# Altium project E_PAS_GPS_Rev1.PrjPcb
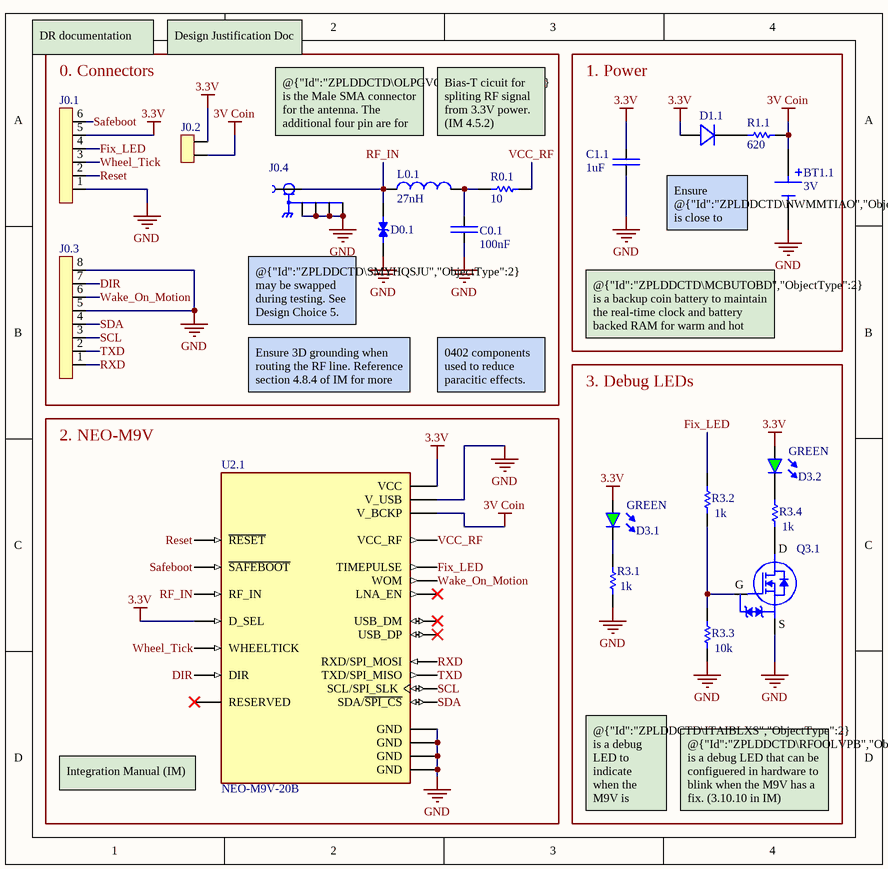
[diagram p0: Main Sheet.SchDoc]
1 sheet, 20 parts. Net scope: global (net labels, ports and power ports of the same name join across sheets).
Board file: Main Sheet.PcbDoc

## Sheet Main Sheet.SchDoc
size 165 x 160 mm; SheetNumber: 1; SheetTotal: 1

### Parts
BT1.1  3V  [BAT_MS621FE-FL11E]
C0.1  value 100nF  [CAPC1005X55N]  (hidden comment: 0402B104K160CT)
C1.1  1uF  [C0805]
D0.1  PESD0402-140  [DIO_PESD0402-140]  (value not drawn)
D1.1  VSKY20301608-G4-08  [VSKY20301608-G4-08-Footprint-1]  (value not drawn)
D3.1  GREEN  [WL-SMCW_0805_150080xx75000]
D3.2  GREEN  [WL-SMCW_0805_150080xx75000]
J0.1  0.1" Header 6pos Male  [0.1" Header 6pos Male-Footprint-1]  (value not drawn)
J0.2  0.1" Header 2pos  [0.1%22 Header 2pos]  (value not drawn)
J0.3  0.1" Header 8pos Male  [0.1" Header 8pos Male-Footprint-1]  (value not drawn)
J0.4  RF2-03E-T-00-50-G  [HUBER+SUHNER_85201239]  (value not drawn)
L0.1  value 27nH  [INDC1005X55N]  (hidden comment: LQG15HS27NJ02D)
Q3.1  DMN3023L-7  [SOT-23-3]  (value not drawn)
R0.1  value 10  [RESC1005X40N]  (hidden comment: RCS040210R0FKED)
R1.1  620  [0805 General Resistor Footprint-Footprint-1]
R3.1  1k  [0805 General Resistor Footprint-Footprint-1]
R3.2  1k  [0805 General Resistor Footprint-Footprint-1]
R3.3  10k  [0805 General Resistor Footprint-Footprint-1]
R3.4  1k  [0805 General Resistor Footprint-Footprint-1]
U2.1  NEO-M9V-20B  [XCVR_NEO-M9V-20B]

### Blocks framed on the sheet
0. Connectors: C0.1 D0.1 J0.1-J0.4 L0.1 R0.1
1. Power: BT1.1 C1.1 D1.1 R1.1
3. Debug LEDs: D3.1 D3.2 Q3.1 R3.1-R3.4
2. NEO-M9V: U2.1

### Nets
3.3V: C1.1.2 D1.1.2 D3.1.2(A) D3.2.2(A) J0.1.5 J0.2.2 U2.1.2(D_SEL) U2.1.23(VCC)
3V Coin: BT1.1.POS J0.2.1 R1.1.1 U2.1.22(V_BCKP)
GND: BT1.1.NEG C0.1.1 C1.1.1 D0.1.1 J0.1.1 J0.3.5 J0.3.8 J0.4.G1 J0.4.G2 J0.4.G3 J0.4.G4 Q3.1.2(S) R3.1.1 R3.3.1 U2.1.7(V_USB) U2.1.10(GND) U2.1.12(GND) U2.1.13(GND) U2.1.24(GND)
DIR: J0.3.7 U2.1.15(DIR)
Fix_LED: J0.1.4 R3.2.2 U2.1.3(TIMEPULSE)
Reset: J0.1.2 U2.1.8(~{RESET})
RF_IN: D0.1.2 J0.4.1 L0.1.1 U2.1.11(RF_IN)
RXD: J0.3.1 U2.1.21(RXD/SPI_MOSI)
Safeboot: J0.1.6 U2.1.1(~{SAFEBOOT})
SCL: J0.3.3 U2.1.19(SCL/SPI_SLK)
SDA: J0.3.4 U2.1.18(SDA/~{SPI_CS})
TXD: J0.3.2 U2.1.20(TXD/SPI_MISO)
VCC_RF: R0.1.2 U2.1.9(VCC_RF)
Wake_On_Motion: J0.3.6 U2.1.17(WOM)
Wheel_Tick: J0.1.3 U2.1.4(WHEELTICK)
NetC0.1_2: C0.1.2 L0.1.2 R0.1.1
NetD1.1_1: D1.1.1 R1.1.2
NetD3.1_1: D3.1.1(K) R3.1.2
NetD3.2_1: D3.2.1(K) R3.4.2
NetQ3.1_1: Q3.1.1(G) R3.2.1 R3.3.2
NetQ3.1_3: Q3.1.3(D) R3.4.1

Not connected (* = marked no-connect by the designer): U2.1 5(USB_DM)* 6(USB_DP)* 14(LNA_EN)* 16(RESERVED)*

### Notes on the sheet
- DR documentation
- DR documentation <https://docs.google.com/document/d/1GB34gBHzcDJZjTo_4NjgQijoAi6lwd67PKlUektAjk4/edit?tab=t.6ztd4vjw2t1h>
- Design Justification Doc
- Design Justification Doc <https://docs.google.com/document/d/1GB34gBHzcDJZjTo_4NjgQijoAi6lwd67PKlUektAjk4/edit?tab=t.6i3rtu1oc2nn>
- @{"Id":"ZPLDDCTD\OLPGVQHD","ObjectType":2} is the Male SMA connector for the antenna. The additional four pin are for shielding.
- Bias-T cicuit for spliting RF signal from 3.3V power. (IM 4.5.2)
- Ensure @{"Id":"ZPLDDCTD\NWMMTIAO","ObjectType":2} is close to VCC.
- (near D0.1) @{"Id":"ZPLDDCTD\SMYHQSJU","ObjectType":2} may be swapped during testing. See Design Choice 5.
- @{"Id":"ZPLDDCTD\MCBUTOBD","ObjectType":2} is a backup coin battery to maintain the real-time clock and battery backed RAM for warm and hot starts. (4.2.2 in IM)
- Ensure 3D grounding when routing the RF line. Reference section 4.8.4 of IM for more details.
- 0402 components used to reduce paracitic effects.
- (near U2.1) Integration Manual (IM)
- (near U2.1) Integration Manual (IM) <https://content.u-blox.com/sites/default/files/NEO-M9V_IntegrationManual_UBX-21029776.pdf>
- @{"Id":"ZPLDDCTD\ITAIBLXS","ObjectType":2} is a debug LED to indicate when the M9V is powered.
- @{"Id":"ZPLDDCTD\RFOOLVPB","ObjectType":2} is a debug LED that can be configuered in hardware to blink when the M9V has a fix. (3.10.10 in IM)

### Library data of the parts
BT1.1 = CMP-104-000009-1: Coin, 6.8mm 3 V Lithium Battery Rechargeable (Secondary) 5.5mAh / MS621FE-FL11E; MF: Seiko Instruments
C0.1 = CMP-156-000012-2: MF: {'manufacturer': u'Walsin Technology Corporation'}
C1.1 = CMP-001-00083-2: Replace name and description with the component intended
D0.1 = CMP-090-000018-1: 40V Clamp - Ipp Tvs Diode Surface Mount 0402; MF: Littelfuse Inc.
D1.1 = CMP-090-000019-2: Rectifier Diode, Schottky, 1 Phase, 1 Element, 2A, 30V V(RRM), Silicon
D3.1 D3.2 = CMP-00065-4: WURTH ELEKTRONIK - 150080GS75000 - LED, Green, SMD, 0805, 30 mA, 3.2 V, 520 nm; Wavelength: 525nm; Power Dissipation: 105mW; Viewing Angle: 140°; Test Current: 20mA; Max Junction Temperature (Tj): 95°C; Forward Voltage: 3.2V; Luminous Intensity: 450mcd; Lens Style: Clear, Rectangular; Peak Wavelength: 515nm; Max Reverse Voltage (DC): 5V; Forward Current: 100mA
J0.1 = CMP-082-000075-5: MP: PH1-06-UA; MF: Adam Tech
J0.2 = CMP-023-0016-3
J0.3 = CMP-082-000068-3: PEC08SAAN --- Board Connector, 8 Contact(s), 1 Row(s), Male, Straight, 0.1 inch Pitch, Solder Terminal
J0.4 = CMP-082-000067-5: SMA Connector Jack, Female Socket 50 Ohms Through Hole, Right Angle Solder; MF: HUBER+SUHNER; MP: 85_SMA-50-0-103/111_NE
L0.1 = CMP-183-000003-3: Inductor with Inductance: 27nH Tol. +/-5%, Package: 0402 _1005_; MF: Murata
Q3.1 = CMP-039-0003-6: N-Channel 30V 6.2A (Ta) 900mW (Ta) Surface Mount SOT-23
R0.1 = CMP-092-000055-2: 10 Ohms Â±1% 0.333W, 1/3W Chip Resistor 0402 (1005 Metric) Automotive AEC-Q200, Pulse Withstanding Thick Film; MF: Vishay Dale
R1.1 R3.1-R3.4 = CMP-009-00226-2: 0805 resisitor
U2.1 = CMP-223-000000-1: NEO-M9V RF Receiver BeiDou, Galileo, GLONASS, GNSS, GPS 1.561GHz -160dBm Not Included; MF: u-blox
